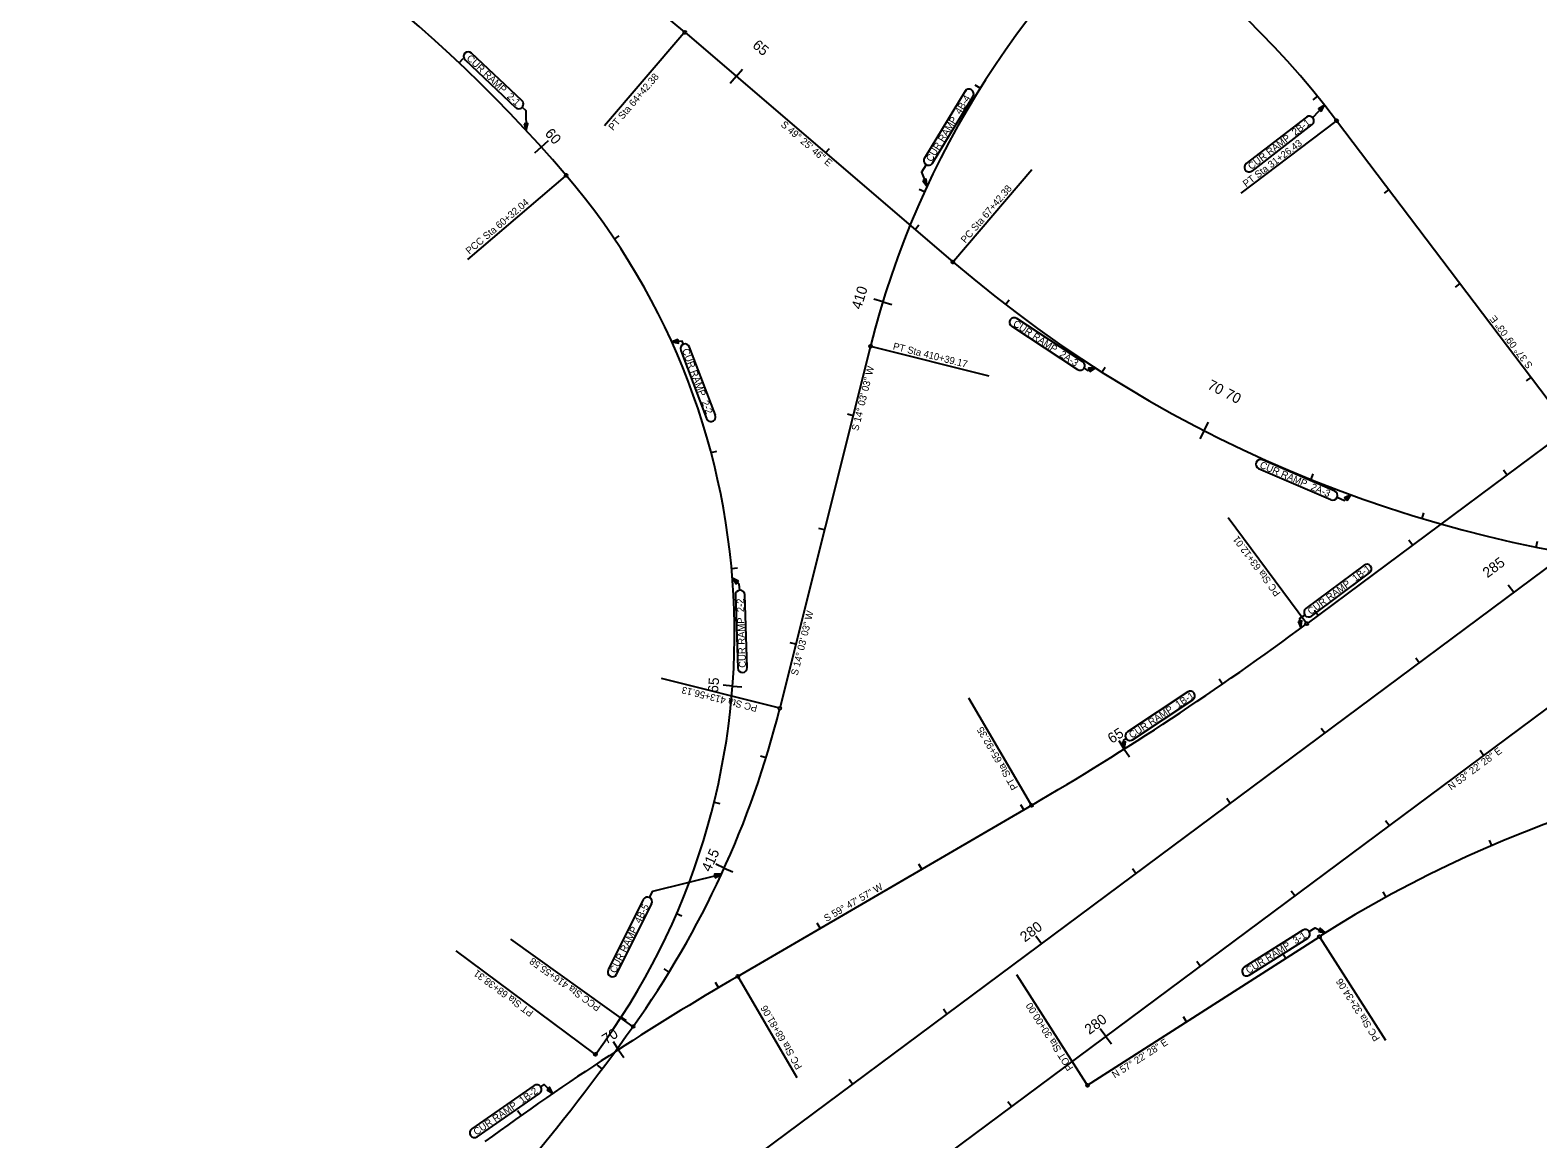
# Model space of a CAD drawing. Extents: x 1603540 to 1622629, y 1083934 to 1103503.
# Drawn here: x 1609107 to 1610388, y 1093124 to 1094065 of the extents above; entities that cross this region are included whole.
import ezdxf

# ---------------------------------------------------------------- set-up
doc = ezdxf.new("R2010")
doc.units = 0
for name, color, linetype in [('RD_EX_BldgChurch', 7, 'Continuous'), ('RD_EX_Fence_ChLk', 7, 'Continuous'), ('RD_EX_H2O', 7, 'Continuous'), ('RD_EX_Misc', 7, 'Continuous'), ('RD_HC_CL', 7, 'Continuous'), ('RD_PG_GR', 7, 'Continuous')]:
    doc.layers.add(name, color=color, linetype=linetype)

msp = doc.modelspace()

# ---------------------------------------------------------------- linework, layer by layer
at = {"layer": 'RD_EX_BldgChurch'}
for p, q in [((1609662.3, 1094062.6), (1609595, 1093984)), ((1610216, 1093987.7), (1610135.5, 1093926.7)), ((1609891.8, 1093869.4), (1609958.1, 1093946.8)), ((1609561.4, 1093941.1), (1609478.5, 1093870.6)), ((1609822.1, 1093796.5), (1609921.4, 1093771.6)), ((1610190.8, 1093562.1), (1610124.8, 1093651)), ((1609742.8, 1093489.6), (1609643.3, 1093514.5)), ((1609957.1, 1093407.9), (1609904.6, 1093498)), ((1609618.2, 1093219.7), (1609515.4, 1093293.1)), ((1610203.1, 1093294.2), (1610258.7, 1093207.4)), ((1609586.2, 1093196.1), (1609468.8, 1093283.3)), ((1609708.8, 1093260.5), (1609758.2, 1093175.7)), ((1610004.6, 1093170.2), (1609945.3, 1093262.8))]:
    msp.add_line(p, q, dxfattribs=at)
for centre in [(1609663.1, 1094063.5), (1610217, 1093988.4), (1609562.3, 1093941.9), (1609891, 1093868.4), (1609820.9, 1093796.8), (1610191.6, 1093561.1), (1609744, 1093489.3), (1609957.7, 1093406.8), (1610202.4, 1093295.3), (1609708.2, 1093261.6), (1609619.2, 1093219), (1609587.2, 1093195.4), (1610005.3, 1093169.1)]:
    msp.add_circle(centre, 1.25, dxfattribs=at)
at = {"layer": 'RD_EX_H2O'}
for p, q in [((1609471.4, 1094037.5), (1609474.8, 1094041.2)), ((1609706.9, 1094026), (1609712.1, 1094032.1)), ((1609706.9, 1094026), (1609701.7, 1094020)), ((1609914.2, 1094015.9), (1609910, 1094018.6)), ((1610200.7, 1094009.2), (1610196.8, 1094006)), ((1609541.2, 1093966), (1609547.2, 1093971.4)), ((1609541.2, 1093966), (1609535.3, 1093960.7)), ((1609782.8, 1093961), (1609786.1, 1093964.8)), ((1609866.9, 1093927.9), (1609862.3, 1093930)), ((1610261.4, 1093929.8), (1610257.5, 1093926.8)), ((1609858.8, 1093896), (1609862, 1093899.8)), ((1609603.3, 1093887.8), (1609607.5, 1093890.6)), ((1610321.8, 1093850.1), (1610317.8, 1093847.1)), ((1609831.4, 1093834.5), (1609823.8, 1093836.9)), ((1609831.4, 1093834.5), (1609839.1, 1093832.2)), ((1609935.7, 1093832.1), (1609938.7, 1093836.1)), ((1609652, 1093800.5), (1609656.5, 1093802.6)), ((1610017.6, 1093774.8), (1610020.3, 1093779)), ((1610382.2, 1093770.4), (1610378.2, 1093767.4)), ((1609806.2, 1093737.8), (1609801.3, 1093739)), ((1610104.4, 1093725.2), (1610100.8, 1093718.1)), ((1610104.4, 1093725.2), (1610108.1, 1093732.3)), ((1609685.5, 1093706.4), (1609690.3, 1093707.7)), ((1610195.3, 1093683.7), (1610197.2, 1093688.3)), ((1610361.7, 1093687.6), (1610358.7, 1093691.6)), ((1610289.7, 1093650.6), (1610291.1, 1093655.3)), ((1609781.9, 1093640.8), (1609777, 1093642)), ((1610281.5, 1093627.9), (1610278.5, 1093632)), ((1610386.6, 1093626.2), (1610387.6, 1093631.1)), ((1609702.9, 1093608.1), (1609707.9, 1093608.5)), ((1610367.5, 1093587.5), (1610362.7, 1093593.9)), ((1610201.2, 1093568.3), (1610198.2, 1093572.3)), ((1609757.6, 1093543.7), (1609752.8, 1093545)), ((1610287.2, 1093527.9), (1610284.2, 1093531.9)), ((1609703.7, 1093508.2), (1609695.8, 1093508.8)), ((1609703.7, 1093508.2), (1609711.7, 1093507.6)), ((1610120, 1093509.9), (1610117.2, 1093514)), ((1610206.9, 1093468.2), (1610204, 1093472.2)), ((1610036.6, 1093454.7), (1610032.3, 1093461.5)), ((1609732.2, 1093447.1), (1609727.4, 1093448.5)), ((1610036.6, 1093454.7), (1610040.9, 1093448)), ((1610341.9, 1093449.2), (1610339, 1093453.3)), ((1609688, 1093409.6), (1609692.9, 1093408.4)), ((1609951.1, 1093403), (1609948.6, 1093407.3)), ((1610126.7, 1093408.5), (1610123.7, 1093412.6)), ((1610261.7, 1093389.6), (1610258.7, 1093393.6)), ((1610349, 1093372.8), (1610347, 1093377.4)), ((1609696.7, 1093353.6), (1609689.4, 1093356.9)), ((1609696.7, 1093353.6), (1609704, 1093350.3)), ((1609864.6, 1093352.7), (1609862.1, 1093357)), ((1610046.4, 1093348.9), (1610043.5, 1093352.9)), ((1610181.4, 1093329.9), (1610178.5, 1093333.9)), ((1610259.1, 1093329), (1610256.7, 1093333.4)), ((1609656.2, 1093314.9), (1609660.7, 1093312.9)), ((1609778.2, 1093302.4), (1609775.7, 1093306.7)), ((1609966.2, 1093289.2), (1609961.4, 1093295.6)), ((1610173.8, 1093276.9), (1610171.1, 1093281.1)), ((1609649.9, 1093265.3), (1609645.6, 1093267.9)), ((1610101.2, 1093270.3), (1610098.2, 1093274.3)), ((1609691.8, 1093252), (1609689.3, 1093256.3)), ((1609609, 1093226.8), (1609613.2, 1093224.1)), ((1609885.9, 1093229.6), (1609882.9, 1093233.6)), ((1610089.5, 1093223), (1610086.8, 1093227.2)), ((1610020.9, 1093210.6), (1610016.2, 1093217)), ((1609606.8, 1093199.3), (1609602.5, 1093206.1)), ((1609606.8, 1093199.3), (1609611.2, 1093192.6)), ((1610020.9, 1093210.6), (1610025.7, 1093204.2)), ((1609593, 1093183.1), (1609589, 1093186.1)), ((1609805.7, 1093169.9), (1609802.7, 1093173.9)), ((1609940.7, 1093151), (1609937.7, 1093155)), ((1609524, 1093143.3), (1609521.1, 1093147.4))]:
    msp.add_line(p, q, dxfattribs=at)
at = {"layer": 'RD_HC_CL'}
for p, q in [((1609261, 1092765), (1614429, 1096606.7)), ((1611290.5, 1094378), (1610191.6, 1093561.1)), ((1609663.1, 1094063.5), (1609891, 1093868.4)), ((1610217, 1093988.4), (1610529.9, 1093575.5)), ((1609780.9, 1093032.2), (1610899.7, 1093863.9)), ((1609820.9, 1093796.8), (1609744, 1093489.3)), ((1609957.7, 1093406.8), (1609708.2, 1093261.6)), ((1610005.3, 1093169.1), (1610202.4, 1093295.3))]:
    msp.add_line(p, q, dxfattribs=at)
for centre, radius, start, end in [((1610558.2, 1093612.3), 760, 18.4471, 165.9491), ((1608648.5, 1093164.1), 1200, 40.4045, 67.546), ((1609611.3, 1093529.4), 760, 37.1508, 76.5065), ((1609012.7, 1093303.9), 1000, 49.4294, 72.8371), ((1609105.4, 1093553), 600, 323.4116, 40.4045), ((1610606.4, 1094704), 1100, 229.4294, 303.6278), ((1608700.1, 1095567.5), 2500, 300.2008, 306.6256), ((1608967.9, 1093683.5), 800, 324.5024, 345.9491), ((1610741.6, 1092453.1), 1000, 90.0249, 122.6256), ((1610965.7, 1091100.9), 2500, 120.2008, 126.0872), ((1607990.9, 1094380.3), 2000, 306.4947, 324.5024)]:
    msp.add_arc(centre, radius, start, end, dxfattribs=at)
at = {"layer": 'RD_PG_GR'}
for p, q in [((1609524.8, 1094005.4), (1609482, 1094045.8)), ((1609476.5, 1094040), (1609519.3, 1093999.6)), ((1609901.3, 1094013.3), (1609866.8, 1093956.5)), ((1609873.6, 1093952.4), (1609908.2, 1094009.2)), ((1610191.4, 1093991.4), (1610140.3, 1093951.9)), ((1610145.2, 1093945.6), (1610196.3, 1093985.1)), ((1610001.3, 1093783.6), (1609945.3, 1093820.4)), ((1609940.9, 1093813.7), (1609996.9, 1093776.9)), ((1609659.7, 1093793.3), (1609681.6, 1093735.4)), ((1609689.1, 1093738.3), (1609667.2, 1093796.1)), ((1610215.4, 1093673.8), (1610153.9, 1093700.3)), ((1610150.7, 1093692.9), (1610212.2, 1093666.5)), ((1610240.3, 1093610.8), (1610190.9, 1093574.1)), ((1610195.6, 1093567.6), (1610245.1, 1093604.4)), ((1609706.1, 1093585.3), (1609708.1, 1093523.5)), ((1609716.1, 1093523.8), (1609714.1, 1093585.6)), ((1610090.5, 1093503.2), (1610039.2, 1093469.3)), ((1610043.6, 1093462.6), (1610094.9, 1093496.5)), ((1609627.8, 1093326.8), (1609598, 1093267)), ((1609605.2, 1093263.4), (1609635, 1093323.2)), ((1610188.3, 1093300.8), (1610138.5, 1093269.4)), ((1610142.7, 1093262.6), (1610192.6, 1093294.1)), ((1609535.2, 1093168.8), (1609482.1, 1093132)), ((1609486.6, 1093125.4), (1609539.7, 1093162.2))]:
    msp.add_line(p, q, dxfattribs=at)
for points in [[(1609524.9, 1093999.8), (1609528, 1093996.9), (1609528.3, 1093980.1)], [(1610197, 1093990.7), (1610196.9, 1093991), (1610206.6, 1094001.5)], [(1609868.1, 1093951), (1609864.3, 1093944.7), (1609869, 1093932.6)], [(1609662, 1093798.4), (1609661, 1093801.2), (1609652, 1093800.5)], [(1610002.4, 1093778.1), (1610005.3, 1093776.2), (1610012.2, 1093778.5)], [(1610217.5, 1093668.6), (1610223.8, 1093665.9), (1610229.2, 1093670.7)], [(1609709.9, 1093589.5), (1609709.4, 1093594.6), (1609703.6, 1093599.9)], [(1610190.1, 1093568.5), (1610185.5, 1093565.6), (1610186.6, 1093557.6)], [(1610038, 1093463.7), (1610035.8, 1093462.2), (1610036.6, 1093454.7)], [(1609633.2, 1093328.6), (1609635.9, 1093334), (1609694.3, 1093348.3)], [(1610193.8, 1093299.6), (1610198.8, 1093302.8), (1610207.6, 1093298.7)], [(1609540.7, 1093167.8), (1609543.5, 1093169.7), (1609551.1, 1093162.2)]]:
    msp.add_lwpolyline(points, dxfattribs=at)
for points in [[(1610203.8, 1093996.2), (1610206.6, 1094001.5), (1610201.5, 1093998.3)], [(1609526.7, 1093985.8), (1609528.3, 1093980.1), (1609529.8, 1093985.9)], [(1609865.4, 1093937.4), (1609869, 1093932.6), (1609868.3, 1093938.6)], [(1609657.6, 1093802.5), (1609652, 1093800.5), (1609657.9, 1093799.4)], [(1610007.2, 1093775.2), (1610012.2, 1093778.5), (1610006.2, 1093778.1)], [(1610225.9, 1093665.7), (1610229.2, 1093670.7), (1610223.8, 1093668)], [(1609708.9, 1093597.2), (1609703.6, 1093599.9), (1609706.8, 1093594.9)], [(1610184.3, 1093563.1), (1610186.6, 1093557.6), (1610187.4, 1093563.5)], [(1610034.4, 1093460.3), (1610036.6, 1093454.7), (1610037.5, 1093460.7)], [(1609689, 1093345.4), (1609694.3, 1093348.3), (1609688.3, 1093348.4)], [(1610201.7, 1093299.7), (1610207.6, 1093298.7), (1610203, 1093302.5)], [(1609545.9, 1093165.2), (1609551.1, 1093162.2), (1609548.1, 1093167.4)]]:
    msp.add_lwpolyline(points, close=True, dxfattribs=at)
for centre, start, end in [((1609479.2, 1094042.9), 46.6915, 226.6915), ((1609904.7, 1094011.2), 328.6915, 148.6915), ((1609522, 1094002.5), 226.6915, 46.6915), ((1610193.8, 1093988.2), 307.6915, 127.6915), ((1609870.2, 1093954.5), 148.6915, 328.6915), ((1610142.7, 1093948.8), 127.6915, 307.6915), ((1609943.1, 1093817), 56.6915, 236.6915), ((1609663.5, 1093794.7), 20.6915, 200.6915), ((1609999.1, 1093780.3), 236.6915, 56.6915), ((1609685.3, 1093736.8), 200.6915, 20.6915), ((1610152.3, 1093696.6), 66.726, 246.726), ((1610213.8, 1093670.1), 246.726, 66.726), ((1610242.7, 1093607.6), 306.6256, 126.6256), ((1609710.1, 1093585.5), 1.9081, 181.9081), ((1610193.3, 1093570.8), 126.6256, 306.6256), ((1609712.1, 1093523.7), 181.9081, 1.9081), ((1610092.7, 1093499.8), 303.4132, 123.4132), ((1610041.4, 1093465.9), 123.4132, 303.4132), ((1609631.4, 1093325), 333.4958, 153.4958), ((1610190.4, 1093297.5), 302.2724, 122.2724), ((1609601.6, 1093265.2), 153.4958, 333.4958), ((1610140.6, 1093266), 122.2724, 302.2724), ((1609537.5, 1093165.5), 304.7138, 124.7138), ((1609484.4, 1093128.7), 124.7138, 304.7138)]:
    msp.add_arc(centre, 4, start, end, dxfattribs=at)

# ---------------------------------------------------------------- texts
at = {"layer": 'RD_EX_BldgChurch'}
for s, rotation, p in [('PT Sta 64+42.38', 49.4294, (1609602.2, 1093979.5)), ('PT Sta 31+26.43', 37.1508, (1610140.1, 1093931.6)), ('PC Sta 67+42.38', 49.4294, (1609901.6, 1093883.9)), ('PCC Sta 60+32.04', 40.4045, (1609480.1, 1093874.5)), ('PT Sta 410+39.17', 345.9491, (1609839.6, 1093794.2)), ('PC Sta 63+12.01', 126.6256, (1610169.7, 1093587.1)), ('PC Sta 413+56.13', 165.9491, (1609725.3, 1093491.9)), ('PT Sta 65+92.35', 120.2008, (1609946.5, 1093422)), ('PCC Sta 416+55.58', 144.5024, (1609592.2, 1093236.3)), ('PT Sta 68+38.31', 143.4116, (1609535.1, 1093231.6)), ('PC Sta 32+34.06', 122.6256, (1610254.2, 1093208.9)), ('POT Sta 30+00.00', 122.6256, (1609993.5, 1093183.8)), ('PC Sta 68+81.06', 120.2008, (1609763.2, 1093184.7))]:
    msp.add_text(s, height=6, rotation=rotation, dxfattribs=at).set_placement(p)
at = {"layer": 'RD_EX_Fence_ChLk'}
for s, rotation, p in [('S 49%%d 25\' 46" E', 319.4294, (1609744.2, 1093984.2)), ('S 37%%d 09\' 03" E', 127.1508, (1610384, 1093780.6)), ('S 14%%d 03\' 03" W', 75.9491, (1609810.5, 1093724.5)), ('S 14%%d 03\' 03" W', 75.9491, (1609759, 1093516.7)), ('N 53%%d 22\' 28" E', 36.6256, (1610314.4, 1093419.4)), ('S 59%%d 47\' 57" W', 30.2008, (1609783.5, 1093307.7)), ('N 57%%d 22\' 28" E', 32.6256, (1610028.5, 1093174.8))]:
    msp.add_text(s, height=6, rotation=rotation, dxfattribs=at).set_placement(p)
at = {"layer": 'RD_EX_Misc'}
for s, rotation, p in [('65', 319.4294, (1609720, 1094051.3)), ('60', 311.9345, (1609543.7, 1093977.1)), ('410', 72.9965, (1609812.9, 1093827.5)), ('70', 332.848, (1610106.6, 1093761.1)), ('70', 332.848, (1610121.4, 1093753.5)), ('285', 36.6256, (1610345.2, 1093599.7)), ('65', 85.7181, (1609691.4, 1093502.2)), ('65', 32.3173, (1610026, 1093459)), ('415', 65.6451, (1609684.8, 1093349.7)), ('280', 36.6256, (1609952.1, 1093290.3)), ('280', 36.6256, (1610006.9, 1093211.7)), ('70', 32.9267, (1609596.4, 1093203.6))]:
    msp.add_text(s, height=8.75, rotation=rotation, dxfattribs=at).set_placement(p)
at = {"layer": 'RD_PG_GR'}
for s, rotation, p in [('CUR RAMP_2-1', 316.6915, (1609477.2, 1094040.7)), ('CUR RAMP_4B-4', 58.6915, (1609872.8, 1093952.9)), ('CUR RAMP_2B-1', 37.6915, (1610144.5, 1093946.4)), ('CUR RAMP_2A-3', 326.6915, (1609941.5, 1093814.5)), ('CUR RAMP_2-2', 290.6915, (1609660.7, 1093793.6)), ('CUR RAMP_2A-3', 336.726, (1610151.1, 1093693.8)), ('CUR RAMP_1B-1', 36.6256, (1610195.1, 1093568.4)), ('CUR RAMP_2-2', 91.9081, (1609715.1, 1093523.8)), ('CUR RAMP_1B-1', 33.4132, (1610043, 1093463.4)), ('CUR RAMP_4B-5', 63.4958, (1609604.3, 1093263.8)), ('CUR RAMP_3-1', 32.2724, (1610142.2, 1093263.5)), ('CUR RAMP_1B-2', 34.7138, (1609486.1, 1093126.3))]:
    msp.add_text(s, height=6, rotation=rotation, dxfattribs=at).set_placement(p)

doc.saveas('drawing.dxf')
